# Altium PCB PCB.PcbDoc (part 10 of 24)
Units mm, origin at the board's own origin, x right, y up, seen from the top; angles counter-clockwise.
Board outline 100 x 160 mm, 10 copper layers (TOP_L1, L2, L3, L4, L5, L6, L7, L8, L9, BOTTOM_L10), stack 1.946 mm thick; 1358 components, 1149 nets, 6777 pads, 10914 vias.
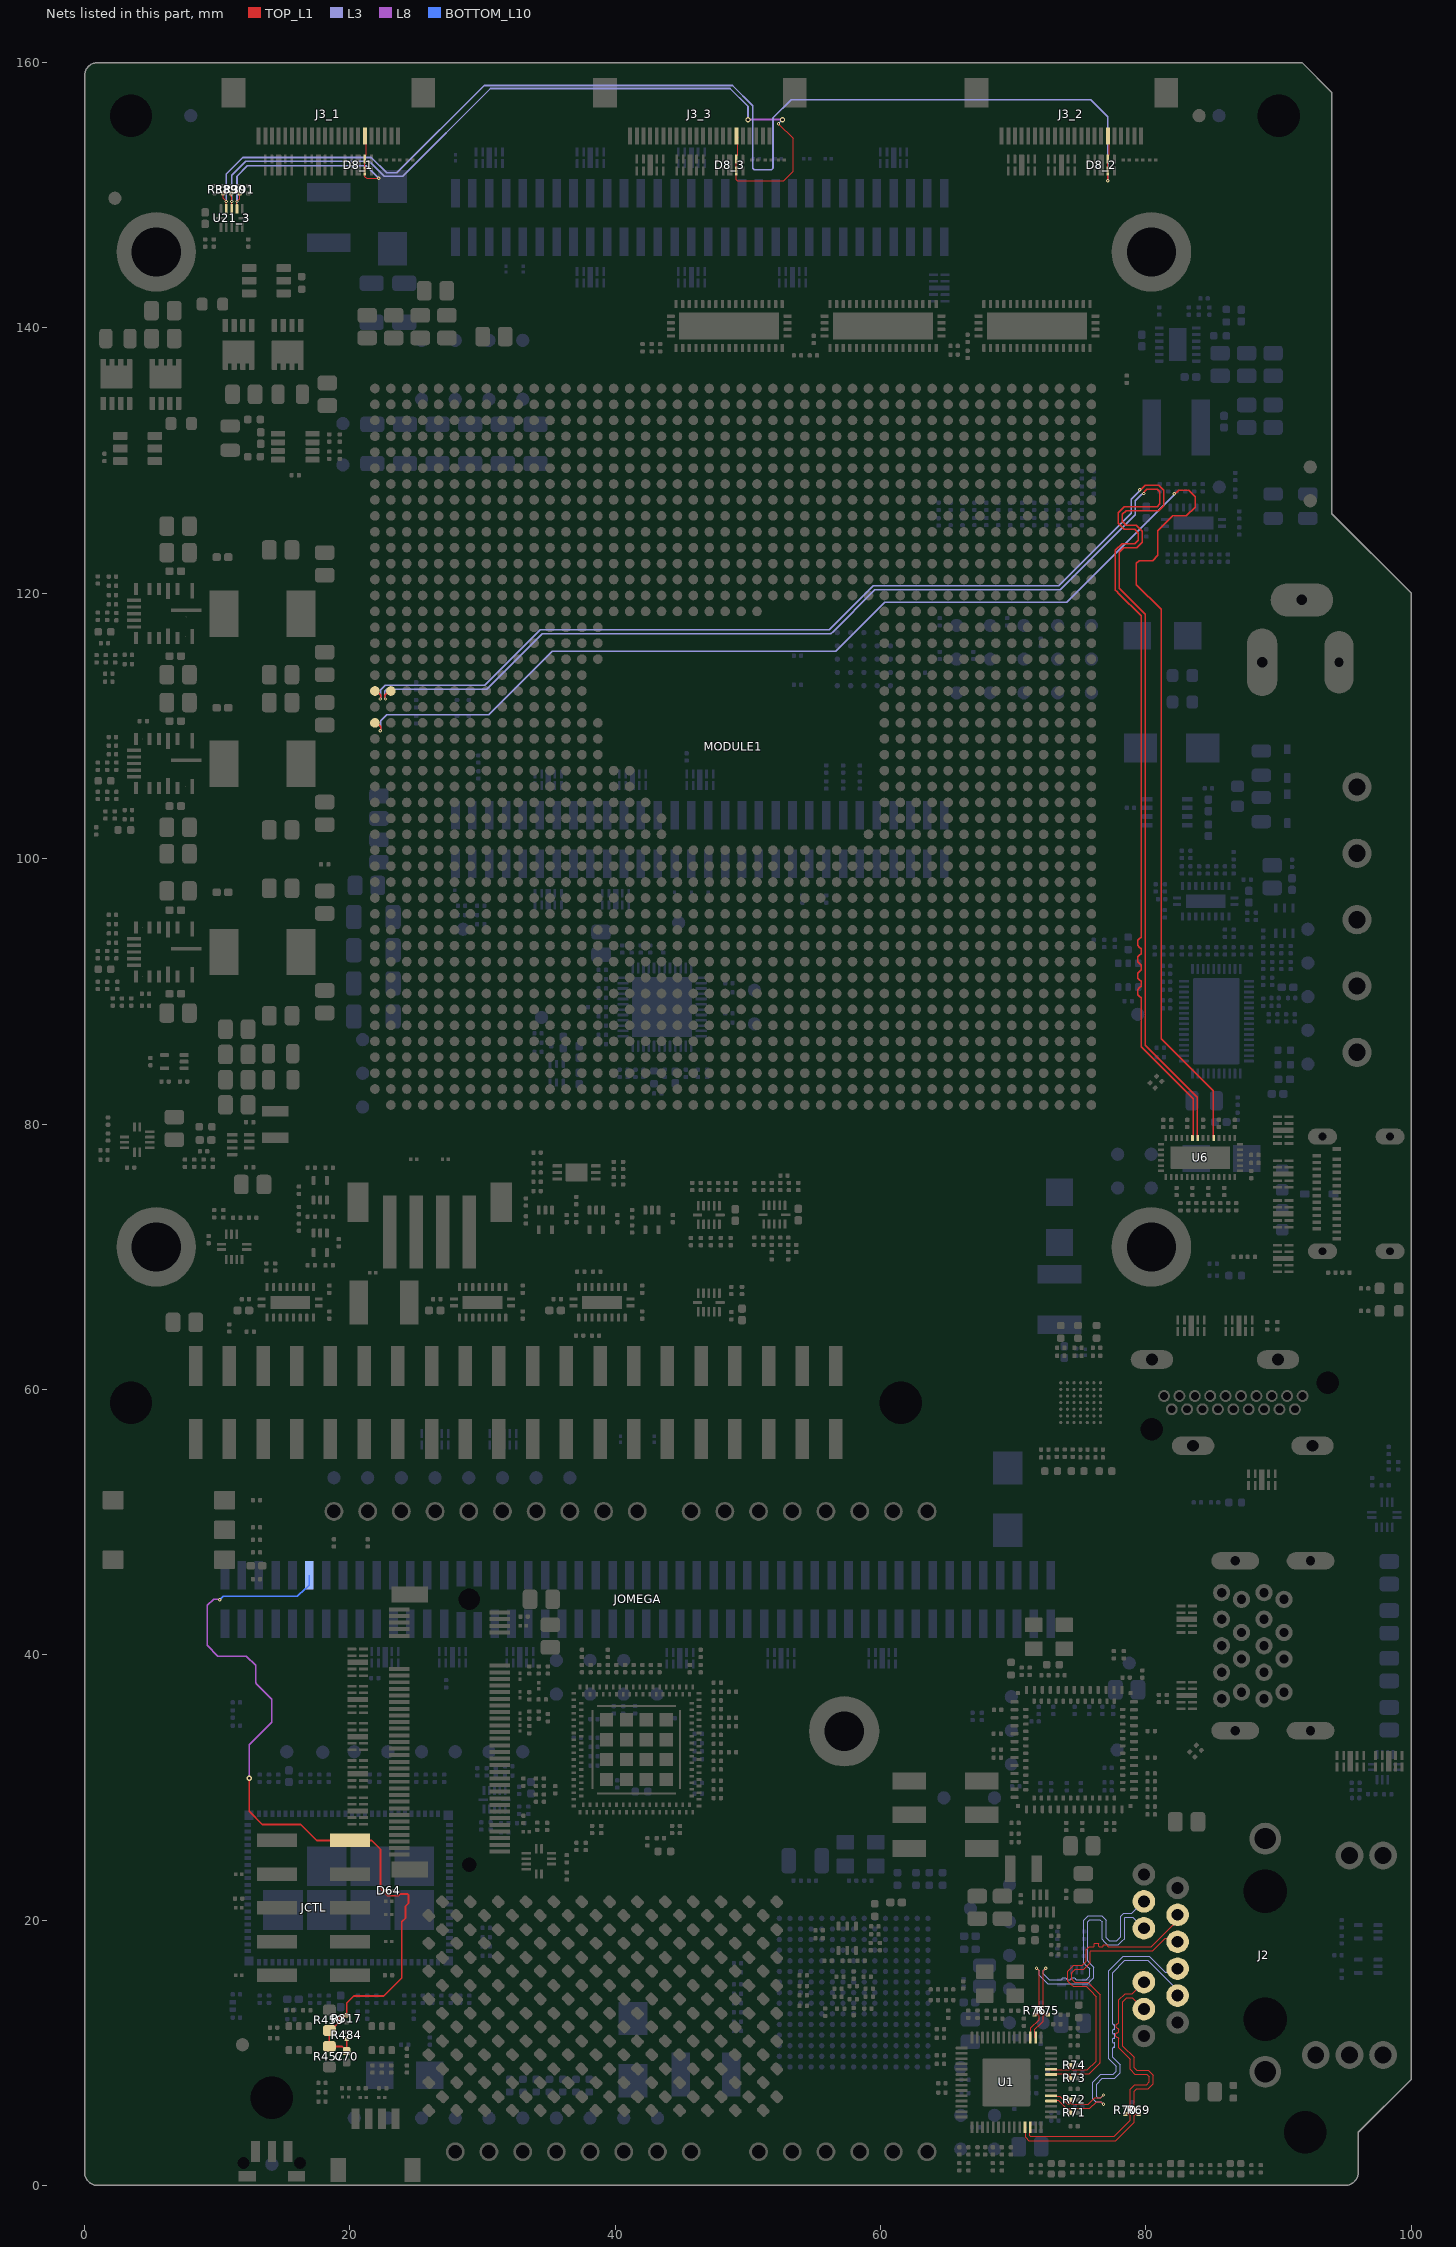
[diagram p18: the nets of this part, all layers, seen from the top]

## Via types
v1: diameter 0.25, hole 0.1, TOP_L1 to L2, tented both sides, 3439 vias
v2: diameter 0.25, hole 0.1, L2 to L3, tented both sides, 2256 vias
v3: diameter 0.25, hole 0.1, L9 to BOTTOM_L10, tented both sides, 1685 vias
v4: diameter 0.25, hole 0.1, L8 to L9, tented both sides, 1675 vias
v5: diameter 0.4, hole 0.2, L3 to L8, tented both sides, 1251 vias
v6: diameter 0.6, hole 0.3, TOP_L1 to BOTTOM_L10, tented both sides, 600 vias
v7: diameter 0.24, hole 0.1, TOP_L1 to L2, tented both sides, 8 vias

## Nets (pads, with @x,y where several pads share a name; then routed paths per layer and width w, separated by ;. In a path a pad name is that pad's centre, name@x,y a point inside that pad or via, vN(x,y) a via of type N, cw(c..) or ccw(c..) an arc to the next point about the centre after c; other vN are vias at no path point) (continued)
EDP0_TX2_P: MODULE1.A25 U6.5 | length 124.2
  TOP_L1 w0.109: MODULE1.A25@21.882,110.236 22.019,110.236 22.33,109.925 22.33,109.77 22.309,109.75 22.309,109.663 v2(22.282,109.636) ; v2(82.136,127.502) 82.174,127.502 82.236,127.563 82.265,127.563 82.464,127.762 83.221,127.762 83.699,127.283 83.699,126.502 83.033,125.836 82.002,125.836 80.892,124.726 80.892,122.855 80.495,122.458 79.482,122.458 79.282,122.258 79.282,120.656 81.136,118.802 81.136,86.436 85.052,82.52 85.052,79.782 85.052,79.174 85.055,79.172 85.055,78.985 U6.5@85.1,78.94
  L3 w0.104: v2(22.282,109.636) 22.31,109.664 22.31,109.75 22.33,109.77 22.33,110.386 22.784,110.841 30.456,110.841 35.256,115.641 56.63,115.641 60.31,119.32 74.022,119.32 79.743,125.041 82.075,127.373 82.075,127.401 82.136,127.462 v2(82.136,127.502)
  other v1: 22.282,109.636 82.136,127.502
EDP0_TX3_N: MODULE1.B27 U6.9 | length 124.2
  TOP_L1 w0.109: v1(22.682,112.036) 22.655,112.063 22.655,112.15 22.634,112.17 22.634,112.325 22.946,112.636 MODULE1.B27@23.082,112.636 ; v2(79.819,127.519) 79.819,127.557 79.881,127.618 79.881,127.648 80.069,127.836 80.845,127.836 81.04,127.641 81.04,126.743 80.833,126.536 78.378,126.536 77.911,126.07 77.911,125.274 78.001,125.185 78.182,125.004 78.36,124.825 79.136,124.825 79.425,124.537 79.425,123.992 79.169,123.736 78.192,123.736 77.693,123.238 77.693,120.241 77.783,120.152 77.961,119.974 79.632,118.303 79.632,94.617 79.632,94.079 79.508,93.956 79.483,93.956 79.36,93.832 79.36,93.462 79.483,93.338 79.508,93.338 79.632,93.215 79.632,92.845 79.508,92.721 79.483,92.721 79.36,92.598 79.36,92.227 79.483,92.104 79.508,92.104 79.632,91.98 79.632,91.61 79.508,91.487 79.483,91.487 79.36,91.363 79.36,90.993 79.483,90.869 79.508,90.869 79.632,90.746 79.632,90.376 79.508,90.252 79.483,90.252 79.36,90.129 79.36,89.758 79.483,89.635 79.508,89.635 79.632,89.512 79.632,89.457 79.632,85.813 83.548,81.897 83.548,79.174 83.545,79.172 83.545,78.985 U6.9@83.5,78.94
  L3 w0.104: v1(22.682,112.036) 22.654,112.064 22.654,112.15 22.634,112.17 22.634,112.619 22.771,112.756 30.302,112.756 34.482,116.936 56.256,116.936 56.435,117.115 59.573,120.253 73.55,120.253 79.202,125.905 79.202,126.969 79.691,127.458 79.719,127.458 79.78,127.519 v2(79.819,127.519)
  other v1: 79.819,127.519
  other v2: 22.682,112.036
EDP0_TX3_P: MODULE1.A27 U6.8 | length 124.2
  TOP_L1 w0.109: MODULE1.A27@21.882,112.636 22.019,112.636 22.33,112.325 22.33,112.17 22.309,112.15 22.309,112.063 v1(22.282,112.036) ; v2(79.536,127.802) 79.574,127.802 79.636,127.863 79.665,127.863 79.943,128.141 80.971,128.141 81.344,127.768 81.344,126.617 80.959,126.231 78.504,126.231 78.216,125.943 78.216,125.401 78.305,125.311 78.487,125.13 79.263,125.13 79.73,124.663 79.73,123.866 79.295,123.431 78.318,123.431 77.998,123.111 77.998,120.368 79.936,118.429 79.936,85.939 83.852,82.023 83.852,79.174 83.855,79.172 83.855,78.985 U6.8@83.9,78.94
  L3 w0.104: v1(22.282,112.036) 22.31,112.064 22.31,112.15 22.33,112.17 22.33,112.746 22.645,113.061 30.176,113.061 34.356,117.241 56.13,117.241 59.447,120.558 73.424,120.558 78.897,126.031 78.897,127.095 79.475,127.673 79.475,127.701 79.536,127.762 v2(79.536,127.802)
  other v1: 79.536,127.802
  other v2: 22.282,112.036
ETH_PHY_TRX0_N: J2.10 R70.2 U1.54 | length 23.6
  TOP_L1 w0.086: U1.54@71.281,4.384 71.233,4.336 71.233,3.74 71.284,3.689 77.589,3.689 78.795,4.895 78.795,5.274 78.695,5.374 ; R70.2@78.448,5.374 78.695,5.374 ; J2.10@79.844,15.32 78.981,14.457 78.426,14.457 77.945,13.976 77.945,13.781 77.945,12.259 77.877,12.191 77.834,12.191 77.766,12.123 77.766,11.918 77.834,11.85 77.877,11.85 77.945,11.782 77.945,11.578 77.877,11.51 77.806,11.51 77.738,11.442 77.738,11.238 77.806,11.17 77.877,11.17 77.945,11.101 77.945,11.058 77.945,10.374 78.795,9.524 78.795,9.016 78.795,8.757 79.168,8.384 80.047,8.384 80.242,8.19 80.242,7.8 80.047,7.606 79.168,7.606 78.795,7.233 78.795,6.863 78.795,5.475 78.695,5.374
ETH_PHY_TRX0_P: J2.11 R69.2 U1.53 | length 23.7
  TOP_L1 w0.086: U1.53@70.881,4.384 70.929,4.336 70.929,3.614 71.158,3.384 77.716,3.384 79.1,4.769 79.1,5.274 79.201,5.374 ; R69.2@79.448,5.374 79.201,5.374 ; J2.11@79.844,13.29 78.981,14.153 78.553,14.153 78.25,13.85 78.25,10.5 79.1,9.65 79.1,9.016 79.1,8.884 79.295,8.689 80.173,8.689 80.546,8.316 80.546,7.674 80.173,7.301 79.295,7.301 79.1,7.106 79.1,6.863 79.1,5.475 79.201,5.374
ETH_PHY_TRX1_N: J2.5 R72.2 U1.5 | length 23.5
  TOP_L1 w0.086: U1.5@72.993,6.711 U1.5@73.262,6.711 ; U1.5@73.263,6.711 73.511,6.711 73.948,6.274 74.1,6.122 74.206,6.122 74.306,6.223 ; R72.2@74.306,6.47 74.306,6.223 ; v1(76.798,6.82) 76.6,6.622 76.149,6.622 75.97,6.444 75.649,6.122 74.407,6.122 74.306,6.223
  L3 w0.084: v1(76.798,6.82) 76.6,6.622 76.323,6.622 76.273,6.671 76.273,7.638 76.706,8.071 77.65,8.071 78.057,8.478 78.057,9.091 77.492,9.656 77.492,9.947 77.492,10.327 cw(c77.576,10.327) 77.576,10.411 77.611,10.411 ccw(c77.611,10.462) 77.661,10.462 77.661,10.698 ccw(c77.611,10.698) 77.611,10.749 77.543,10.749 cw(c77.543,10.8) 77.492,10.8 77.492,11.036 cw(c77.543,11.036) 77.543,11.087 77.611,11.087 ccw(c77.611,11.137) 77.661,11.137 77.661,11.374 ccw(c77.611,11.374) 77.611,11.424 77.543,11.424 cw(c77.543,11.475) 77.492,11.475 77.492,11.712 cw(c77.543,11.712) 77.543,11.762 77.587,11.762 ccw(c77.587,11.813) 77.638,11.813 77.638,12.049 ccw(c77.587,12.049) 77.587,12.1 77.576,12.1 cw(c77.576,12.184) 77.492,12.184 77.492,14.74 77.492,16.047 78.415,16.97 80.134,16.97 81.819,15.285 82.384,14.72 J2.5@82.384,14.305
  other v2: 76.798,6.82
ETH_PHY_TRX1_P: J2.4 R71.2 U1.4 | length 23.5
  TOP_L1 w0.086: U1.4@72.904,6.406 73.385,6.406 73.973,5.818 74.206,5.818 74.306,5.717 ; R71.2@74.306,5.47 74.306,5.717 ; v1(76.798,6.12) 76.6,6.318 76.275,6.318 75.775,5.818 74.407,5.818 74.306,5.717
  L3 w0.084: v1(76.798,6.12) 76.6,6.318 76.196,6.318 75.969,6.545 75.969,7.764 76.58,8.375 77.524,8.375 77.752,8.604 77.752,8.965 77.187,9.53 77.187,16.173 78.289,17.274 80.26,17.274 81.457,16.077 82.227,16.077 82.384,15.92 J2.4@82.384,16.335
  other v2: 76.798,6.12
ETH_PHY_TRX2_N: J2.2 R74.2 U1.10 | length 23.7
  TOP_L1 w0.086: U1.10@72.856,8.759 72.904,8.711 74.206,8.711 74.306,8.812 ; R74.2@74.306,9.059 74.306,8.812 ; J2.2@82.384,20.395 82.384,19.984 81.816,19.416 81.329,18.928 80.38,17.979 78.884,17.979 77.168,17.979 77.117,18.03 77.117,18.103 77.066,18.154 76.828,18.154 76.777,18.103 76.777,18.03 76.726,17.979 76.487,17.979 76.436,18.03 76.436,18.201 76.385,18.252 76.147,18.252 76.096,18.201 76.096,18.03 76.045,17.979 76.002,17.979 75.713,17.979 75.484,17.75 75.484,16.895 75.189,16.6 74.546,16.6 74.367,16.421 74.105,16.159 74.105,15.406 74.337,15.174 74.516,14.995 75.484,14.995 75.784,14.695 76.243,14.236 76.243,9.372 75.582,8.711 74.407,8.711 74.306,8.812
ETH_PHY_TRX2_P: J2.3 R73.2 U1.9 | length 23.7
  TOP_L1 w0.086: U1.9@72.856,8.359 72.904,8.407 74.206,8.407 74.306,8.306 ; R73.2@74.306,8.059 74.306,8.306 ; 76.548,9.613 76.548,10.089 ; 76.548,10.293 76.548,10.77 ; J2.3@82.384,18.365 82.384,18.776 82.231,18.624 81.455,18.624 80.506,17.674 75.839,17.674 75.789,17.624 75.789,16.769 75.315,16.295 74.672,16.295 74.41,16.032 74.41,15.532 74.642,15.3 75.61,15.3 76.548,14.363 76.548,11.542 76.548,9.246 ; 74.306,8.306 74.407,8.407 75.511,8.407 75.708,8.407 76.458,9.157 ; 76.458,9.157 76.548,9.246 ; 76.458,9.157 76.531,9.229 76.548,9.246
ETH_PHY_TRX3_N: J2.9 R76.2 U1.17 | length 23.5
  TOP_L1 w0.086: U1.17@71.281,11.134 71.329,11.182 71.329,11.882 71.507,12.061 71.757,12.31 71.948,12.501 71.948,12.774 71.847,12.875 ; R76.2@71.6,12.875 71.847,12.875 ; v1(71.75,16.375) 71.948,16.177 71.948,13.34 71.948,12.976 71.847,12.875
  L3 w0.084: v1(71.75,16.375) 71.948,16.177 71.948,15.832 72.583,15.196 75.616,15.196 76.057,15.637 76.057,16.458 75.768,16.747 75.599,16.916 75.599,19.864 75.763,20.028 76.526,20.028 76.689,19.866 76.689,18.54 76.867,18.361 77.094,18.134 77.919,18.134 78.208,18.423 78.386,18.601 78.386,20.156 78.436,20.206 79.019,20.206 J2.9@79.844,19.38
  other v2: 71.75,16.375
ETH_PHY_TRX3_P: J2.8 R75.2 U1.16 | length 23.4
  TOP_L1 w0.086: U1.16@71.681,11.134 71.633,11.182 71.633,11.756 72.061,12.184 72.252,12.375 72.252,12.774 72.353,12.875 ; v2(72.45,16.375) 72.252,16.177 72.252,12.976 72.353,12.875 ; R75.2@72.6,12.875 72.353,12.875
  L3 w0.084: v2(72.45,16.375) 72.252,16.177 72.252,15.958 72.71,15.501 73.28,15.501 73.627,15.501 73.677,15.551 73.677,15.609 73.728,15.659 73.965,15.659 74.015,15.609 74.015,15.551 74.066,15.501 74.302,15.501 74.353,15.551 74.353,15.609 74.404,15.659 74.64,15.659 74.691,15.609 74.691,15.551 74.742,15.501 75.121,15.501 75.49,15.501 75.752,15.763 75.752,16.332 75.472,16.612 75.294,16.79 75.294,19.99 75.637,20.333 76.653,20.333 76.994,19.992 76.994,18.666 77.221,18.439 77.793,18.439 78.082,18.728 78.082,20.283 78.309,20.51 78.944,20.51 J2.8@79.844,21.41
  other v1: 72.45,16.375
FLAT0_GPIO_PIN17_3V3_41: D8_2.4 D8_2.7 J3_2.17 R389.1 U21_3.10 | length 92.1
  TOP_L1 w0.084: R389.1@10.436,150.15 10.436,149.79 10.686,149.54 U21_3.10@10.686,148.975
  TOP_L1 w0.086: D8_2.4@77.124,151.842 D8_2.7@77.124,152.717 77.124,152.954 77.222,153.052 77.222,153.682 77.222,154.377 J3_2.17@77.124,154.475
  TOP_L1 w0.127: v2(77.124,151.093) D8_2.4@77.124,151.842
  L3 w0.127: v2(10.686,149.53) 10.686,151.598 11.93,152.842 21.611,152.842 22.767,151.686 23.533,151.686 30.125,158.278 48.84,158.278 50.369,156.748 50.369,152.037 50.481,151.925 51.77,151.925 51.882,152.037 51.882,155.835 53.257,157.21 75.837,157.21 77.124,155.922 v2(77.124,151.093)
  other v1: 10.686,149.53 77.124,151.093
FLAT1_GPIO_PIN17_3V3_41: D8_3.4 D8_3.7 J3_3.17 R390.1 U21_3.9 | length 62.4
  TOP_L1 w0.084: R390.1@11.036,150.15 11.036,149.888 11.086,149.838 v1(11.086,149.531) U21_3.9@11.086,148.975
  TOP_L1 w0.086: J3_3.17@49.124,154.475 49.222,154.377 49.222,153.682 49.222,153.052 49.124,152.954 D8_3.7@49.124,152.717 D8_3.4@49.124,151.842 49.124,151.155 49.2,151.079 52.679,151.079 53.4,151.8 53.4,154.3 v1(52.3,155.4)
  L3 w0.086: v1(52.3,155.4) v5(52.6,155.7)
  L3 w0.127: v1(11.086,149.531) 11.086,151.502 12.145,152.561 21.456,152.561 22.582,151.435 23.982,151.435 30.598,158.051 48.649,158.051 50,156.7 v5(50,155.7)
  L8 w0.15: v5(50,155.7) v5(52.6,155.7)
  other v2: 11.086,149.531 52.3,155.4
FLAT2_GPIO_PIN17_3V3_41: D8_1.4 D8_1.7 J3_1.17 R391.1 U21_3.8 | length 18.8
  TOP_L1 w0.084: U21_3.8@11.486,148.975 v1(11.486,149.53) 11.686,149.731 R391.1@11.686,150.15
  TOP_L1 w0.086: J3_1.17@21.124,154.475 21.222,154.377 21.222,153.682 21.222,153.052 21.124,152.954 D8_1.7@21.124,152.717 D8_1.4@21.124,151.842 21.126,151.84 21.126,151.404 21.255,151.275 v2(22.169,151.275)
  L3 w0.127: v1(11.486,149.53) 11.486,151.442 12.267,152.223 21.222,152.223 v2(22.169,151.275)
  other v1: 22.169,151.275
  other v2: 11.486,149.53
FORCE_BOOT_3V3_1: C70.1 D64.2 JCTL.2 JOMEGA.89 R317.1 R457.2 R459.2 R484.1 | length 63.1
  TOP_L1 w0.127: v1(12.4,30.7) 12.4,28.2 13.4,27.2 16.3,27.2 17.499,26.001 JCTL.2@20.01,26.001 21.632,26.001 22.31,25.323 22.31,22.395 22.484,22.221 D64.2@22.685,22.221 D64.2@22.694,22.221 ; R484.1@19.75,11.025 C70.1@19.75,10.135 19.41,10.475 R457.2@18.45,10.475 R459.2@18.45,11.675 18.554,11.675 19.2,12.321 19.2,12.662 19.263,12.725 19.75,12.725 R317.1@19.75,12.825 19.75,13.75 20.281,14.281 22.56,14.281 23.909,15.63 23.909,19.867 24.183,20.141 24.183,21.041 24.41,21.268 24.41,21.889 24.336,21.963 23.787,21.963 23.651,21.827 22.848,21.827 22.71,21.965 D64.2@22.71,22.221
  L8 w0.1: v4(10.183,44.149) 10.138,44.194 9.729,44.194 9.252,43.717 9.252,40.695 10.047,39.9 12.2,39.9 12.903,39.197 12.903,37.893 12.936,37.86 12.936,37.801 14.1,36.637 14.1,34.9 12.4,33.2 v1(12.4,30.7)
  BOTTOM_L10 w0.1: v4(10.183,44.149) 10.435,44.4 16.041,44.4 16.616,44.975 16.661,44.975 16.936,45.25 JOMEGA.89@16.936,46
  other v2: 12.4,30.7
  other v3: 10.183,44.149
  other v5: 12.4,30.7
